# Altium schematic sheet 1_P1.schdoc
size 429 x 358 mm; Symbol: Sheet-Symbol_A4; Device: Sheet-Symbol_A4; Company: 嘉立创EDA; Drawed: Solituder; Version: V4.0; Page Size: A4; @Project Name: FOC12; @Page Count: 1; @Update Date: 2025-03-15; @Create Date: 2024-12-24; @Schematic Name: Schematic2; @Page No: 1; @Page Name: P1; @Board Name: 控制板; @Create Time: 09:32:19; @Update Time: 14:25:51; Width: 1655; Height: 1370; Region Start: 2; X Region Count: 6; Y Region Count: 4; Blade Width: 10; Title Block Position: 3
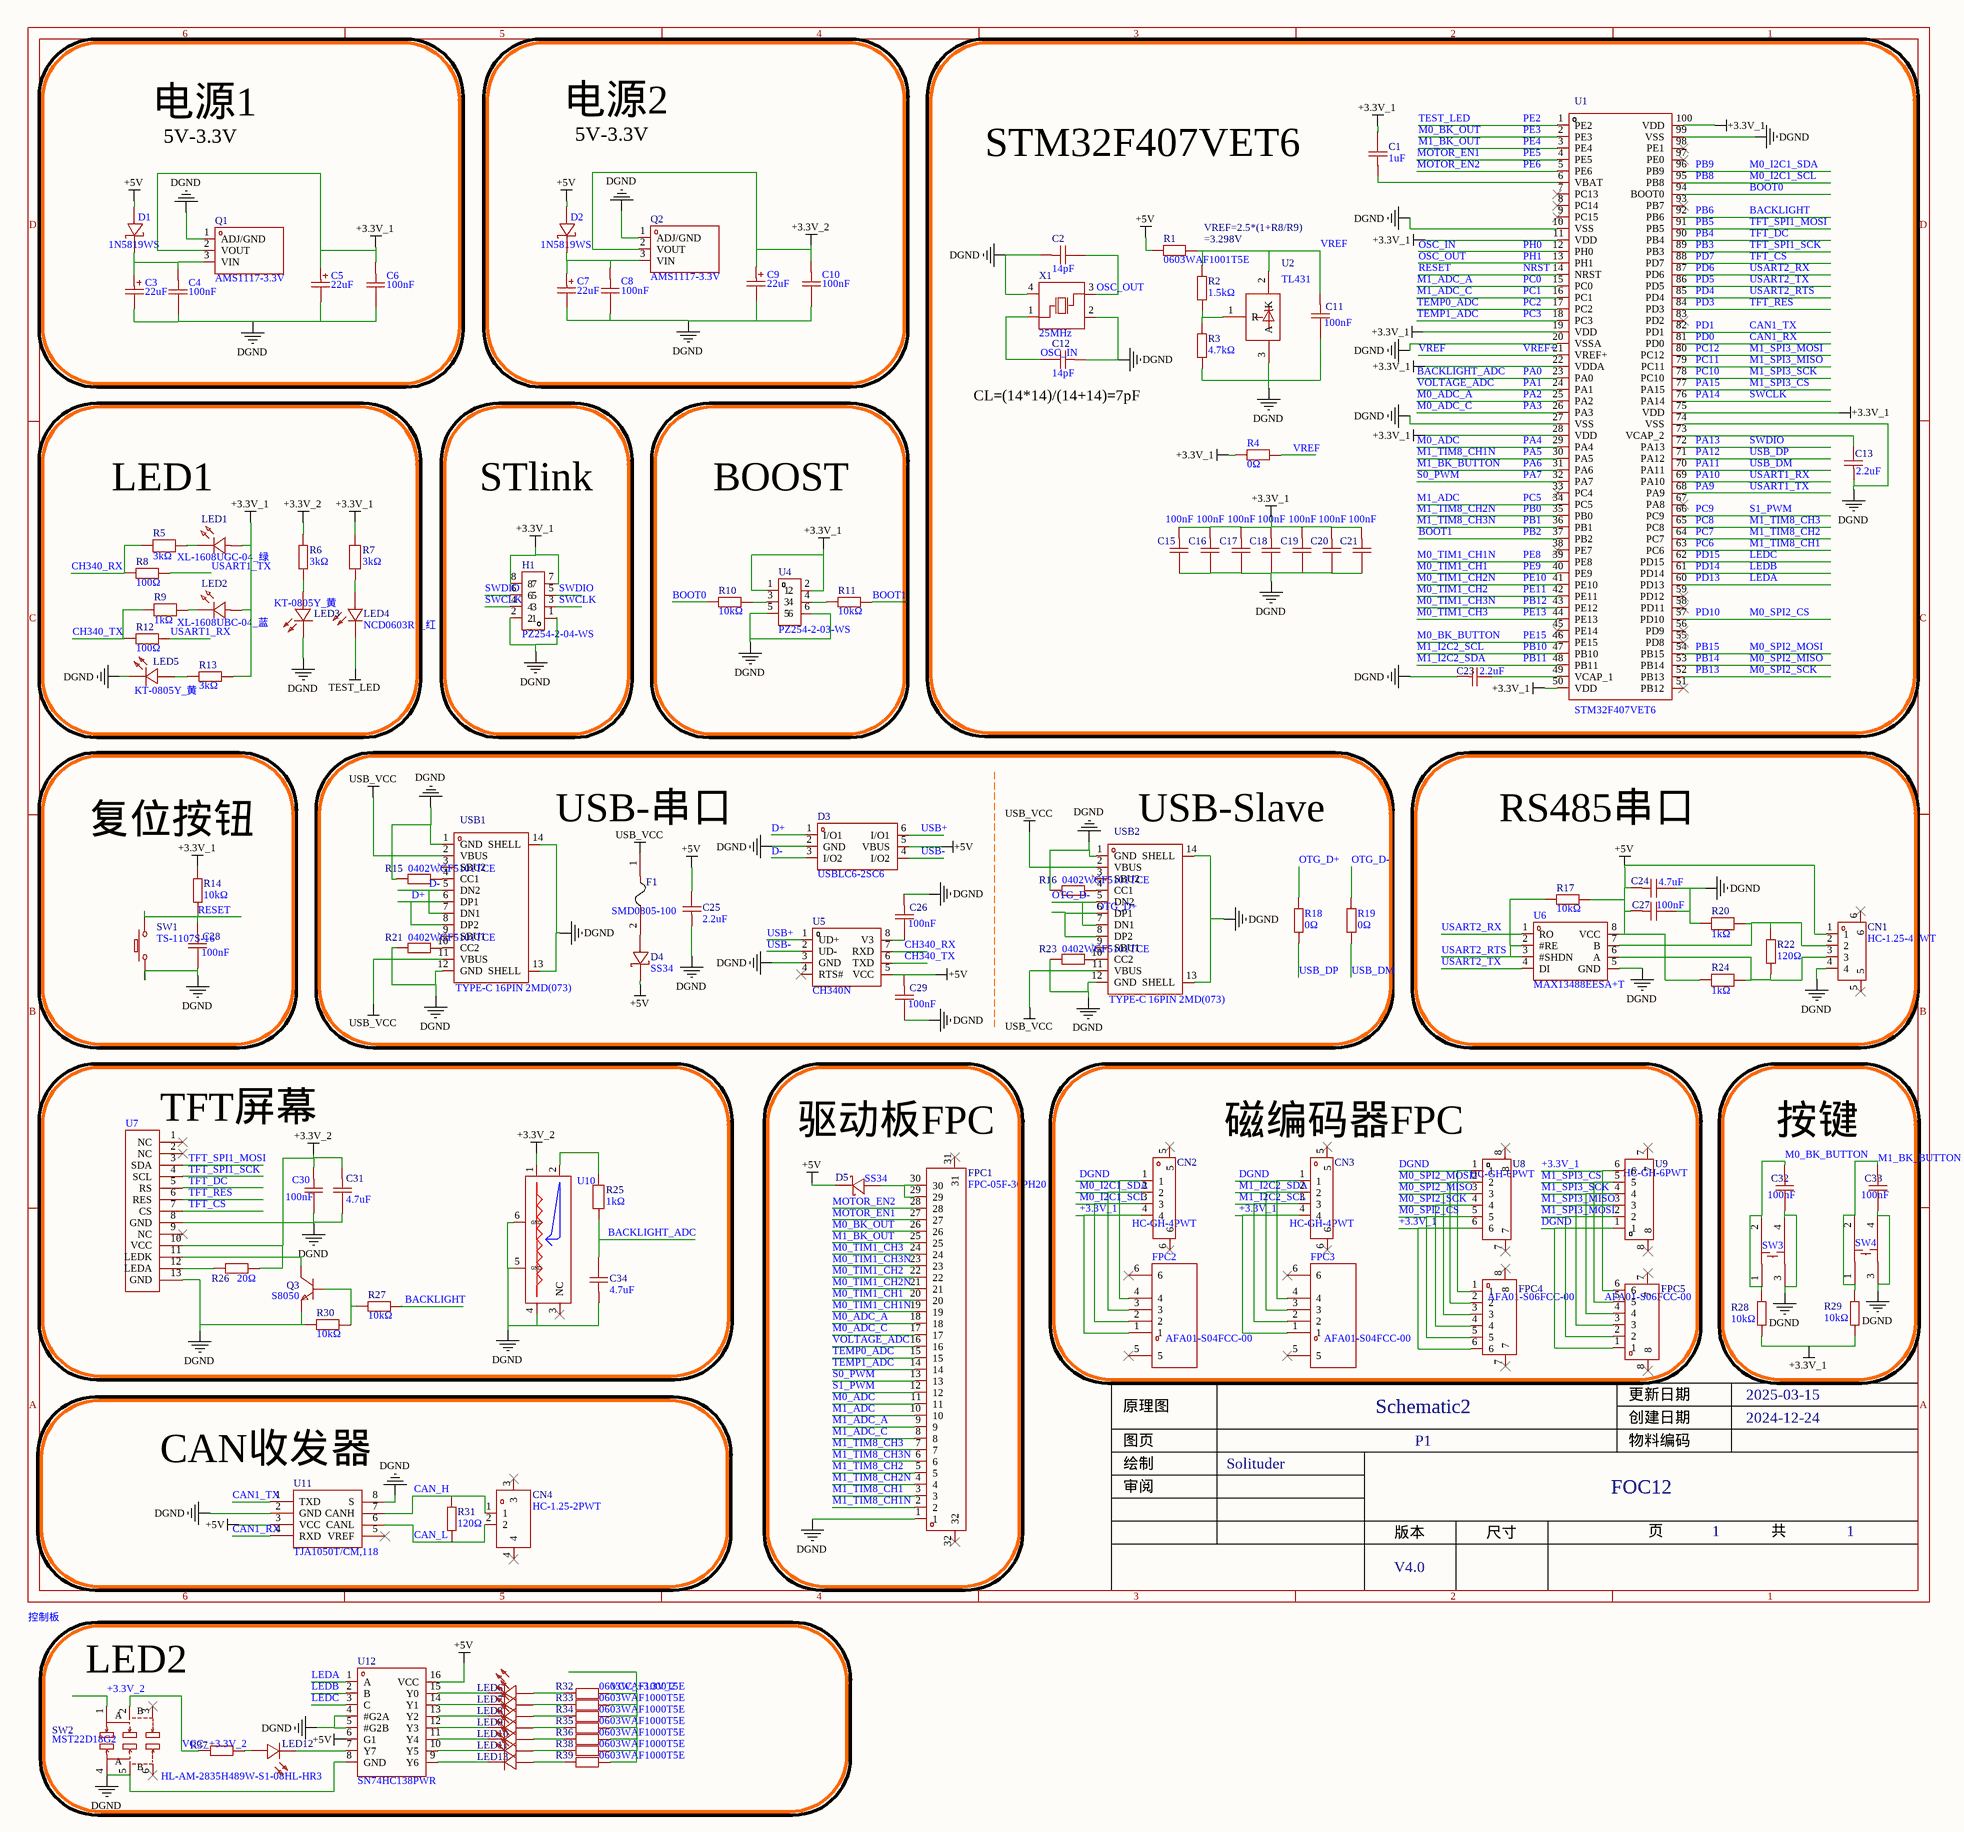
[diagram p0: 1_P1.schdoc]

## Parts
C1  1uF  [C0603]
C2  14pF  [C0402]
C3  22uF  [CASE-A_3216]
C4  100nF  [C0603]
C5  22uF  [CASE-A_3216]
C6  100nF  [C0603]
C7  22uF  [CASE-A_3216]
C8  100nF  [C0603]
C9  22uF  [CASE-A_3216]
C10  100nF  [C0603]
C11  100nF  [C0603]
C12  14pF  [C0402]
C13  2.2uF  [C0603]
C15  100nF  [C0603]
C16  100nF  [C0603]
C17  100nF  [C0603]
C18  100nF  [C0603]
C19  100nF  [C0603]
C20  100nF  [C0603]
C21  100nF  [C0603]
C23  2.2uF  [C0603]
C24  4.7uF  [C0603]
C25  2.2uF  [C0603]
C26  100nF  [C0603]
C27  100nF  [C0603]
C28  100nF  [C0603]
C29  100nF  [C0603]
C30  100nF  [C0603]
C31  4.7uF  [C0603]
C32  100nF  [C0603]
C33  100nF  [C0603]
C34  4.7uF  [C0603]
CN1  HC-1.25-4PWT  [CONN-SMD_4P-P1.25-HC-1.25-4PWT]
CN2  HC-GH-4PWT  [CONN-SMD_HC-GH-4PWT]
CN3  HC-GH-4PWT  [CONN-SMD_HC-GH-4PWT]
CN4  HC-1.25-2PWT  [CONN-SMD_2P-P1.25-HC-1.25-2PWT]
D1  1N5819WS  [SOD-323_L1.8-W1.3-LS2.5-RD]
D2  1N5819WS  [SOD-323_L1.8-W1.3-LS2.5-RD]
D3  USBLC6-2SC6  [SOT-23-6_L2.9-W1.6-P0.95-LS2.8-BL]
D4  SS34  [SMA_L4.3-W2.6-LS5.2-RD]
D5  SS34  [SMA_L4.3-W2.6-LS5.2-RD]
F1  SMD0805-100  [F0805]
FPC1  FPC-05F-30PH20  [FPC-SMD_30P-P0.50_XUNPU_FPC-05F-30PH20]
FPC2  AFA01-S04FCC-00  [FPC-SMD_AFA01-S04FCC-00]
FPC3  AFA01-S04FCC-00  [FPC-SMD_AFA01-S04FCC-00]
FPC4  AFA01-S06FCC-00  [FPC-SMD_6P-P1.00_AFA01-S06]
FPC5  AFA01-S06FCC-00  [FPC-SMD_6P-P1.00_AFA01-S06]
H1  PZ254-2-04-WS  [HDR-SMD_8P-P2.54-H-M-R2-C4_2]
LED1  XL-1608UGC-04_绿  [LED0603-RD_GREEN]
LED2  XL-1608UBC-04_蓝  [LED0603-RD_BLUE]
LED3  KT-0805Y_黄  [LED0805-R-RD]
LED4  NCD0603R1_红  [LED0603-RD_RED]
LED5  KT-0805Y_黄  [LED0805-R-RD]
LED6  HL-AM-2835H489W-S1-08HL-HR3  [LED-SMD_L3.3-W2.8-RD]  (value not drawn)
LED7  HL-AM-2835H489W-S1-08HL-HR3  [LED-SMD_L3.3-W2.8-RD]  (value not drawn)
LED8  HL-AM-2835H489W-S1-08HL-HR3  [LED-SMD_L3.3-W2.8-RD]  (value not drawn)
LED9  HL-AM-2835H489W-S1-08HL-HR3  [LED-SMD_L3.3-W2.8-RD]  (value not drawn)
LED10  HL-AM-2835H489W-S1-08HL-HR3  [LED-SMD_L3.3-W2.8-RD]  (value not drawn)
LED11  HL-AM-2835H489W-S1-08HL-HR3  [LED-SMD_L3.3-W2.8-RD]  (value not drawn)
LED12  HL-AM-2835H489W-S1-08HL-HR3  [LED-SMD_L3.3-W2.8-RD]
LED13  HL-AM-2835H489W-S1-08HL-HR3  [LED-SMD_L3.3-W2.8-RD]  (value not drawn)
Q1  AMS1117-3.3V  [SOT-89-3_L4.5-W2.5-P1.50-LS4.2-BR]
Q2  AMS1117-3.3V  [SOT-89-3_L4.5-W2.5-P1.50-LS4.2-BR]
Q3  S8050  [SOT-23-3_L2.9-W1.3-P1.90-LS2.4-BR]
R1  0603WAF1001T5E  [R0603]
R2  1.5kΩ  [R0603]
R3  4.7kΩ  [R0603]
R4  0Ω  [R0603]
R5  3kΩ  [R0402]
R6  3kΩ  [R0603]
R7  3kΩ  [R0402]
R8  100Ω  [R0402]
R9  1kΩ  [R0402]
R10  10kΩ  [R0402]
R11  10kΩ  [R0402]
R12  100Ω  [R0402]
R13  3kΩ  [R0603]
R14  10kΩ  [R0402]
R15  0402WGF5101TCE  [R0402]
R16  0402WGF5101TCE  [R0402]
R17  10kΩ  [R0402]
R18  0Ω  [R0603]
R19  0Ω  [R0603]
R20  1kΩ  [R0402]
R21  0402WGF5101TCE  [R0402]
R22  120Ω  [R0603]
R23  0402WGF5101TCE  [R0402]
R24  1kΩ  [R0402]
R25  1kΩ  [R0402]
R26  20Ω  [R0402]
R27  10kΩ  [R0402]
R28  10kΩ  [R0402]
R29  10kΩ  [R0402]
R30  10kΩ  [R0402]
R31  120Ω  [R0603]
R32  0603WAF1000T5E  [R0603]
R33  0603WAF1000T5E  [R0603]
R34  0603WAF1000T5E  [R0603]
R35  0603WAF1000T5E  [R0603]
R36  0603WAF1000T5E  [R0603]
R37  0603WAF1000T5E  [R0603]  (value not drawn)
R38  0603WAF1000T5E  [R0603]
R39  0603WAF1000T5E  [R0603]
SW1  TS-1107S-16  [SW-SMD_L6.0-W3.7-LS8.0]
SW2  MST22D18G2  [SW-SMD_MST22D18G2]
SW3  K2-1808SN-A3SW-01  [椭圆白头按钮开关]  (value not drawn)
SW4  K2-1808SN-A3SW-01  [椭圆白头按钮开关]  (value not drawn)
U1  STM32F407VET6  [LQFP-100_L14.0-W14.0-P0.50-LS16.0-BL]
U2  TL431  [SOT-23-3_L2.9-W1.4-P1.90-LS2.6-BR]
U4  PZ254-2-03-WS  [HDR-SMD_6P-P2.54-H-M-R2-C3-LS17.0]
U5  CH340N  [SOP-8_L4.9-W3.9-P1.27-LS6.0-BL]
U6  MAX13488EESA+T  [SOIC-8_L5.0-W4.0-P1.27-LS6.0-BL]
U7  (no value)  [1.14 TFT_13P]
U8  HC-GH-6PWT  [CONN-SMD_6P-P1.25_HCTL_HC-GH-6PWT]
U9  HC-GH-6PWT  [CONN-SMD_6P-P1.25_HCTL_HC-GH-6PWT]
U10  (no value)  [RS08U111Z001]
U11  TJA1050T/CM,118  [SOIC-8_L5.0-W4.0-P1.27-LS6.0-BL]
U12  SN74HC138PWR  [TSSOP-16_L5.0-W4.4-P0.65-LS6.4-BL]
USB1  TYPE-C 16PIN 2MD(073)  [USB-C-SMD_TYPE-C-6PIN-2MD-073]
USB2  TYPE-C 16PIN 2MD(073)  [USB-C-SMD_TYPE-C-6PIN-2MD-073]
X1  25MHz  [CRYSTAL-SMD_4P-L3.2-W2.5-BL]

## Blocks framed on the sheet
电源1: C3-C6 D1 Q1
电源2: C7-C10 D2 Q2
STM32F407VET6: C1 C2 C11-C13 C15-C21 C23 R1-R4 U1 U2 X1
LED1: LED1-LED5 R5-R9 R12 R13
STlink: H1
BOOST: R10 R11 U4
复位按钮: C28 R14 SW1
RS485串口: C24 C27 CN1 R17 R20 R22 R24 U6
TFT屏幕: C30 C31 C34 Q3 R25-R27 R30 U7 U10
驱动板FPC: D5 FPC1
磁编码器FPC: CN2 CN3 FPC2-FPC5 U8 U9
按键: C32 C33 R28 R29 SW3 SW4
CAN收发器: CN4 R31 U11
LED2: LED6-LED13 R32-R39 SW2 U12

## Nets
+3.3V_1: C1.1 C5.1 C6.2 C15.2 C16.2 C17.2 C18.2 C19.2 C20.2 C21.2 CN2.4 CN3.4 FPC2.1 FPC3.1 FPC4.6 FPC5.6 H1.7 H1.8 LED1.2(A) LED2.2(A) Q1.2(VOUT) R4.1 R7.2 R13.2 R14.2 R28.1 R29.1 U1.11(VDD) U1.19(VDD) U1.22(VDDA) U1.28(VDD) U1.50(VDD) U1.75(VDD) U1.100(VDD) U4.1 U4.2 U8.6 U9.6
+3.3V_2: C9.1 C10.2 C30.2 C31.2 Q2.2(VOUT) R6.2 R26.2 SW2.1 U7.10(VCC) U10.1(V/G)
+5V: C24.2 C25.2 C27.2 C29.2 CN1.1 D1.2(A) D2.2(A) D3.5(VBUS) D4.1(K) D5.1(K) R1.1 R17.1 R24.2 U5.5(VCC) U6.8(VCC) U11.3(VCC) U12.6(G1) U12.16(VCC)
DGND: C2.2 C3.2 C4.1 C5.2 C6.1 C7.2 C8.1 C9.2 C10.1 C11.1 C12.2 C13.1 C15.1 C16.1 C17.1 C18.1 C19.1 C20.1 C21.1 C23.1 C24.1 C25.1 C26.2 C27.1 C28.1 C29.1 C30.1 C31.1 C32.1 C33.1 C34.2 CN1.4 CN2.1 CN3.1 D3.2(GND) FPC1.1 FPC2.4 FPC3.4 FPC4.1 FPC5.1 H1.1 H1.2 LED3.2(-) LED5.2(-) Q1.1(ADJ/GND) Q2.1(ADJ/GND) Q3.2(E) R3.1 R15.1 R16.1 R20.2 R21.1 R23.1 R30.2 SW1.1 SW2.4 SW2.5 SW3.3 SW3.4 SW4.3 SW4.4 U1.10(VSS) U1.20(VSSA) U1.27(VSS) U1.74(VSS) U1.99(VSS) U2.3(A) U4.5 U4.6 U5.3(GND) U6.5(GND) U7.8(GND) U7.13(GND) U8.1 U9.1 U10.4(V/G) U10.5(GND) U10.6(GND) U11.2(GND) U11.8(S) U12.4(#G2A) U12.5(#G2B) U12.8(GND) USB1.1(GND) USB1.12(GND) USB1.13(SHELL) USB1.14(SHELL) USB2.1(GND) USB2.12(GND) USB2.13(SHELL) USB2.14(SHELL) X1.2(GND) X1.4(GND)
PE2: LED4.1(K) U1.1(PE2)  [also labelled TEST_LED]
USB_VCC: F1.1 USB1.2(VBUS) USB1.11(VBUS) USB2.2(VBUS) USB2.11(VBUS)
BACKLIGHT: R27.1 U1.92(PB6)  [also labelled PB6]
BACKLIGHT_ADC: C34.1 R25.1 U1.23(PA0)  [also labelled PA0]
BOOT0: R10.1 U1.94(BOOT0)
BOOT1: R11.1 U1.37(PB2)  [also labelled PB2]
CAN1_RX: U1.81(PD0) U11.4(RXD)  [also labelled PD0]
CAN1_TX: U1.82(PD1) U11.1(TXD)  [also labelled PD1]
CAN_H: CN4.1 R31.2 U11.7(CANH)
CAN_L: CN4.2 R31.1 U11.6(CANL)
CH340_RX: R5.2 R8.1 U5.7(RXD)
CH340_TX: R9.2 R12.1 U5.6(TXD)
D+: D3.1(I/O1) USB1.6(DP1) USB1.8(DP2)
D-: D3.3(I/O2) USB1.5(DN2) USB1.7(DN1)
LEDA: U1.60(PD13) U12.1(A)  [also labelled PD13]
LEDB: U1.61(PD14) U12.2(B)  [also labelled PD14]
LEDC: U1.62(PD15) U12.3(C)  [also labelled PD15]
M0_ADC: FPC1.11 U1.29(PA4)  [also labelled PA4]
M0_ADC_A: FPC1.18 U1.25(PA2)  [also labelled PA2]
M0_ADC_C: FPC1.17 U1.26(PA3)  [also labelled PA3]
M0_BK_BUTTON: C32.2 R28.2 SW3.1 SW3.2 U1.46(PE15)  [also labelled PE15]
M0_BK_OUT: FPC1.26 U1.2(PE3)  [also labelled PE3]
M0_I2C1_SCL: CN2.3 FPC2.2 U1.95(PB8)  [also labelled PB8]
M0_I2C1_SDA: CN2.2 FPC2.3 U1.96(PB9)  [also labelled PB9]
M0_SPI2_CS: FPC4.5 U1.57(PD10) U8.5  [also labelled PD10]
M0_SPI2_MISO: FPC4.3 U1.53(PB14) U8.3  [also labelled PB14]
M0_SPI2_MOSI: FPC4.2 U1.54(PB15) U8.2  [also labelled PB15]
M0_SPI2_SCK: FPC4.4 U1.52(PB13) U8.4  [also labelled PB13]
M0_TIM1_CH1: FPC1.20 U1.40(PE9)  [also labelled PE9]
M0_TIM1_CH1N: FPC1.19 U1.39(PE8)  [also labelled PE8]
M0_TIM1_CH2: FPC1.22 U1.42(PE11)  [also labelled PE11]
M0_TIM1_CH2N: FPC1.21 U1.41(PE10)  [also labelled PE10]
M0_TIM1_CH3: FPC1.24 U1.44(PE13)  [also labelled PE13]
M0_TIM1_CH3N: FPC1.23 U1.43(PE12)  [also labelled PB12]
M1_ADC: FPC1.10 U1.34(PC5)  [also labelled PC5]
M1_ADC_A: FPC1.9 U1.15(PC0)  [also labelled PC0]
M1_ADC_C: FPC1.8 U1.16(PC1)  [also labelled PC1]
M1_BK_BUTTON: C33.2 R29.2 SW4.1 SW4.2 U1.31(PA6)  [also labelled PA6]
M1_BK_OUT: FPC1.25 U1.3(PE4)  [also labelled PE4]
M1_I2C2_SCL: CN3.3 FPC3.2 U1.47(PB10)  [also labelled PB10]
M1_I2C2_SDA: CN3.2 FPC3.3 U1.48(PB11)  [also labelled PB11]
M1_SPI3_CS: FPC5.5 U1.77(PA15) U9.5  [also labelled PA15]
M1_SPI3_MISO: FPC5.3 U1.79(PC11) U9.3  [also labelled PC11]
M1_SPI3_MOSI: FPC5.2 U1.80(PC12) U9.2  [also labelled PC12]
M1_SPI3_SCK: FPC5.4 U1.78(PC10) U9.4  [also labelled PC10]
M1_TIM8_CH1: FPC1.3 U1.63(PC6)  [also labelled PC6]
M1_TIM8_CH1N: FPC1.2 U1.30(PA5)  [also labelled PA5]
M1_TIM8_CH2: FPC1.5 U1.64(PC7)  [also labelled PC7]
M1_TIM8_CH2N: FPC1.4 U1.35(PB0)  [also labelled PB0]
M1_TIM8_CH3: FPC1.7 U1.65(PC8)  [also labelled PC8]
M1_TIM8_CH3N: FPC1.6 U1.36(PB1)  [also labelled PB1]
MOTOR_EN1: FPC1.27 U1.4(PE5)  [also labelled PE5]
MOTOR_EN2: FPC1.28 U1.5(PE6)  [also labelled PE6]
NRST: C28.2 R14.1 SW1.2 U1.14(NRST)  [also labelled RESET]
OSC_IN: C12.1 U1.12(PH0) X1.1(OSC1)  [also labelled PH0]
OSC_OUT: C2.1 U1.13(PH1) X1.3(OSC2)  [also labelled PH1]
OTG_D+: R18.1 USB2.6(DP1) USB2.8(DP2)
OTG_D-: R19.1 USB2.5(DN2) USB2.7(DN1)
PA1: FPC1.16 U1.24(PA1)  [also labelled VOLTAGE_ADC]
PA7: FPC1.13 U1.32(PA7)  [also labelled S0_PWM]
PA9: R8.2 U1.68(PA9)  [also labelled USART1_TX]
PA10: R12.2 U1.69(PA10)  [also labelled USART1_RX]
PA11: R19.2 U1.70(PA11)  [also labelled USB_DM]
PA12: R18.2 U1.71(PA12)  [also labelled USB_DP]
PA13: H1.5 H1.6 U1.72(PA13)  [also labelled SWDIO]
PA14: H1.3 H1.4 U1.76(PA14)  [also labelled SWCLK]
PB3: U1.89(PB3) U7.4(SCL)  [also labelled TFT_SPI1_SCK]
PB4: U1.90(PB4) U7.5(RS)  [also labelled TFT_DC]
PB5: U1.91(PB5) U7.3(SDA)  [also labelled TFT_SPI1_MOSI]
PC2: FPC1.15 U1.17(PC2)  [also labelled TEMP0_ADC]
PC3: FPC1.14 U1.18(PC3)  [also labelled TEMP1_ADC]
PC9: FPC1.12 U1.66(PC9)  [also labelled S1_PWM]
PD3: U1.84(PD3) U7.6(RES)  [also labelled TFT_RES]
PD4: R17.2 U1.85(PD4) U6.2(#RE) U6.3(#SHDN)  [also labelled USART2_RTS]
PD5: U1.86(PD5) U6.4(DI)  [also labelled USART2_TX]
PD6: U1.87(PD6) U6.1(RO)  [also labelled USART2_RX]
PD7: U1.88(PD7) U7.7(CS)  [also labelled TFT_CS]
USB+: D3.6(I/O1) U5.1(UD+)
USB-: D3.4(I/O2) U5.2(UD-)
VCC_+3.3V_2: R32.2 R33.2 R34.2 R35.2 R36.2 R37.2 R38.2 R39.2 SW2.2
VREF: C11.2 R1.2 R2.2 R4.2 U1.21(VREF+) U2.2(K)  [also labelled VREF+]
NetC1_2: C1.2 U1.6(VBAT)
NetC3_1: C3.1 C4.2 D1.1(K) Q1.3(VIN)
NetC7_1: C7.1 C8.2 D2.1(K) Q2.3(VIN)
NetC13_2: C13.2 U1.73(VCAP_2)
NetC23_2: C23.2 U1.49(VCAP_1)
NetC26_1: C26.1 U5.8(V3)
NetCN1_2: CN1.2 R20.1 R22.2 U6.7(B)
NetCN1_3: CN1.3 R22.1 R24.1 U6.6(A)
NetD4_2: D4.2(A) F1.2
NetD5_2: D5.2(A) FPC1.29 FPC1.30
NetLED1_1: LED1.1(K) R5.1
NetLED2_1: LED2.1(K) R9.1
NetLED3_1: LED3.1(+) R6.1
NetLED4_2: LED4.2(A) R7.1
NetLED5_1: LED5.1(+) R13.1
NetLED6_1: LED6.1 U12.15(Y0)
NetLED6_2: LED6.2 R32.1
NetLED7_1: LED7.1 U12.14(Y1)
NetLED7_2: LED7.2 R33.1
NetLED8_1: LED8.1 U12.13(Y2)
NetLED8_2: LED8.2 R34.1
NetLED9_1: LED9.1 U12.12(Y3)
NetLED9_2: LED9.2 R35.1
NetLED10_1: LED10.1 U12.11(Y4)
NetLED10_2: LED10.2 R36.1
NetLED11_1: LED11.1 U12.10(Y5)
NetLED11_2: LED11.2 R38.1
NetLED12_1: LED12.1 U12.7(Y7)
NetLED12_2: LED12.2 R37.1
NetLED13_1: LED13.1 U12.9(Y6)
NetLED13_2: LED13.2 R39.1
NetQ3_1: Q3.1(B) R27.2 R30.1
NetQ3_3: Q3.3(C) U7.11(LEDK)
NetR2_1: R2.1 R3.2 U2.1(R)
NetR10_2: R10.2 U4.3
NetR11_2: R11.2 U4.4
NetR15_2: R15.2 USB1.4(CC1)
NetR16_2: R16.2 USB2.4(CC1)
NetR21_2: R21.2 USB1.10(CC2)
NetR23_2: R23.2 USB2.10(CC2)
NetR25_2: R25.2 U10.2(OUT)
NetR26_1: R26.1 U7.12(LEDA)

Not connected (* = marked no-connect by the designer): CN1 5* 6*; CN2 5* 6*; CN3 5* 6*; CN4 3* 4*; FPC1 31* 32*; FPC2 5* 6*; FPC3 5* 6*; FPC4 7* 8*; FPC5 7* 8*; SW2 3* 6*; U1 7(PC13)* 8(PC14)* 9(PC15)* 33(PC4)* 38(PE7)* 45(PE14)* 51(PB12)* 55(PD8)* 56(PD9)* 58(PD11)* 59(PD12)* 67(PA8)* 83(PD2)* 93(PB7)* 97(PE0)* 98(PE1)*; U5 4(RTS#)*; U7 1(NC)* 2(NC)* 9(NC)*; U8 7* 8*; U9 7* 8*; U10 3(NC)*; U11 5(VREF)*; USB1 3(SBU2)* 9(SBU1)*; USB2 3(SBU2)* 9(SBU1)*

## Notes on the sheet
- 5V-3.3V
- VREF=2.5*(1+R8/R9)
  =3.298V
- (near C12) CL=(14*14)/(14+14)=7pF
- USB-串口
- (near USB2) USB-Slave

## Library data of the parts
C1 = CL10A105KB8NNNC: Manufacturer: SAMSUNG(三星); Add into BOM: yes; Tolerance: ±10%; Voltage Rated: 50V; Temperature Coefficient: X5R
C2 C12 = 0402CG140J500NT: Manufacturer: FH(风华); Add into BOM: yes; Tolerance: ±5%; Voltage Rated: 50V; Temperature Coefficient: C0G
C3 C5 C7 C9 = TAJA226K010RNJ: Manufacturer: Kyocera AVX; Add into BOM: yes; Tolerance: ±10%; Rated Voltage: 10V; Equivalent Series Resistance(ESR): 3Ω@100kHz
C4 C6 C8 C10 C30 = CC0603KRX7R9BB104: Manufacturer: YAGEO(国巨); Add into BOM: yes; Tolerance: ±10%; Voltage Rated: 50V; Temperature Coefficient: X7R
C11 C15-C21 C26-C29 C32 C33 = CGA0603X7R104K500JT: Manufacturer: HRE(芯声); Add into BOM: yes; Tolerance: ±10%; Voltage Rated: 50V; Temperature Coefficient: X7R
C13 C23 C25 = CL10A225KO8NNNC: Manufacturer: SAMSUNG(三星); Add into BOM: yes; Tolerance: ±10%; Voltage Rated: 16V; Temperature Coefficient: X5R
C24 C31 C34 = CL10A475KO8NNNC: Manufacturer: SAMSUNG(三星); Add into BOM: yes; Tolerance: ±10%; Voltage Rated: 16V; Temperature Coefficient: X5R
CN1 = HC-1.25-4PWT: Manufacturer: HCTL(华灿天禄); Add into BOM: yes; Pins Structure: 1x4P; Pitch: 1.25mm; Reference Series: PicoBlade(MX 1.25); Number of PINs Per Row: 4; Current Rating (Max): 1A; Rated Voltage (Max): 125V; Plastic Material: LCP; Flame Retardant Rating: UL94V-0; Supplementary Features: 辅助焊脚; Z-Height of the Board: 3.57mm; X-Length of Bottom Edge on Board (Spacing Line): 10.05mm; Y-Width of Bottom Edge on Board: 5.25mm
CN2 CN3 = HC-GH-4PWT_C2845399: Manufacturer: HCTL(华灿天禄); Add into BOM: yes; Pins Structure: 1x4P; Pitch: 1.25mm; Reference Series: GH; Number of PINs Per Row: 4; Current Rating (Max): 1A; Rated Voltage (Max): 50V; Plastic Material: LCP; Flame Retardant Rating: UL94V-0; Supplementary Features: 辅助焊脚; Z-Height of the Board: 4.25mm; X-Length of Bottom Edge on Board (Spacing Line): 8.25mm
CN4 = HC-1.25-2PWT: Manufacturer: HCTL(华灿天禄); Add into BOM: yes; Pins Structure: 1x2P; Pitch: 1.25mm; Reference Series: PicoBlade(MX 1.25); Number of PINs Per Row: 2; Current Rating (Max): 1A; Rated Voltage (Max): 125V; Plastic Material: LCP; Flame Retardant Rating: UL94V-0; Supplementary Features: 辅助焊脚; Z-Height of the Board: 3.57mm; X-Length of Bottom Edge on Board (Spacing Line): 7.55mm; Y-Width of Bottom Edge on Board: 5.25mm
D1 D2 = 1N5819WS_C191023: Manufacturer: Hottech(合科泰); Add into BOM: yes; Reverse Voltage (Vr): 40V; Average Rectified Current (Io): 1A; Forward Voltage (Vf@If): 600mV@1A
D3 = USBLC6-2SC6: Manufacturer: UMW(友台半导体); Symbol: USBLC6-2SC6_C2687116; Add into BOM: yes; Maximum Clamping Voltage: 15V; Breakdown Voltage: 6V; Number of Lines: 双路; Type: ESD
D4 D5 = SS34_C8678: Manufacturer: MDD(辰达半导体); Add into BOM: yes; Diode Configuration: 独立式; Forward Voltage (Vf@If): 550mV@3A; Reverse Voltage (Vr): 40V; Rectified Current: 3A; Reverse Leakage Current (Ir): 500uA@40V
F1 = SMD0805-100: Manufacturer: 台湾陆海; Add into BOM: yes; Operating Voltage (Max): 6V; Current Rating (Max): 100A; Hold Current: 1A; Trip Current: 1.95A
FPC1 = FPC-05F-30PH20: Manufacturer: XUNPU(讯普); Add into BOM: yes; Locking Feature: 翻盖式; Number of Contacts: 30P; Pitch: 0.5mm; FFC, FCB Thickness: 0.3mm
FPC2 FPC3 = AFA01-S04FCC-00: Manufacturer: JS(钜硕电子); Add into BOM: yes; Pitch: 1mm; Number of Contacts: 4; Locking Feature: 翻盖式; FFC, FCB Thickness: 0.3mm
FPC4 FPC5 = AFA01-S06FCC-00: Manufacturer: JS(钜硕电子); Add into BOM: yes; Locking Feature: 翻盖式; Number of Contacts: 6; Pitch: 1mm; FFC, FCB Thickness: 0.3mm
H1 = PZ254-2-04-WS: Manufacturer: HCTL(华灿天禄); Add into BOM: yes; Pin Structure: 2x4P; Pitch: 2.54mm; Circluar Pins/Square Pins: 方针; Current Rating (Max): 3A; Soldering Temperature(Max): 260℃@10S
LED1 = XL-1608UGC-04: Manufacturer: XINGLIGHT(成兴光); Add into BOM: yes; Emitted Color: 翠绿色; Power Dissipation: 80mW; Forward Current: 25mA; Dominant Wavelength: 516nm~525nm; Peak Wavelength: 534nm; Diode Configuration: 独立二极管; Lens Color: 无色透明透镜; Viewing Angle: 120°; Mounting Sytle: 正贴
LED2 = XL-1608UBC-04: Manufacturer: XINGLIGHT(成兴光); Add into BOM: yes; Emitted Color: 蓝色; Power Dissipation: 80mW; Forward Current: 25mA; Dominant Wavelength: 460nm~469nm; Peak Wavelength: 475nm; Lens Color: 无色透明透镜; Viewing Angle: 120°; Mounting Sytle: 正贴
LED3 LED5 = KT-0805Y: Manufacturer: KENTO; Symbol: 17-21SUYC/TR8; Add into BOM: yes; Emitted Color: 黄色
LED4 = NCD0603R1_C84263: Manufacturer: 国星光电; Symbol: FC-DA1608HRK-620D; Add into BOM: yes; Forward Current: 25mA; Diode Configuration: 独立二极管; Luminous Intensity: 80mcd~220mcd; Viewing Angle: 130°; Illumination Color: 红色; Voltage - Forward(Vf): 1.6V~2.6V; Power(Watts): 65mW; Wavelength - Dominant: 615nm~630nm
LED6-LED13 = HL-AM-2835H489W-S1-08HL-HR3: Manufacturer: HONGLITRONIC(鸿利光电); Symbol: HL-AM-2835H489W-S1-08HL-HR3_C210310; Add into BOM: yes; Emitted Color: 白灯; Color Temperature: 2800K~3100K; Mounting Sytle: 正贴
Q1 Q2 = AMS1117-3.3V_C5120796: Manufacturer: MSKSEMI(美森科); Add into BOM: yes; Output Type: 固定; Maximum Input Voltage: 18V; Output Voltage: 3.3V; MAX Output Current: 1A; Dropout Voltage: 1.4V@(1A); standby current: 12mA; Output Polarity: 正极; Number of Outputs: 1
Q3 = S8050: Manufacturer: Doeshare(德芯); Symbol: S8050_C2931719; Add into BOM: yes
R1 = 0603WAF1001T5E: Manufacturer: UNI-ROYAL(厚声); Add into BOM: yes
R2 = 0603WAF1501T5E: Manufacturer: UNI-ROYAL(厚声); Add into BOM: yes; Tolerance: ±1%; Power(Watts): 1/10W; Overload Voltage (Max): 75V; Temperature Coefficient: ±100ppm/℃
R3 = RC0603FR-074K7L: Manufacturer: YAGEO(国巨); Add into BOM: yes; Tolerance: ±1%; Power(Watts): 100mW; Overload Voltage (Max): 75V; Temperature Coefficient: ±100ppm/℃
R4 R18 R19 = 0603WAF0000T5E: Manufacturer: UNI-ROYAL(厚声); Add into BOM: yes; Tolerance: ±1%; Power(Watts): 1/10W; Overload Voltage (Max): 75V
R5 R7 = FRC0402F3001TS: Manufacturer: FOJAN(富捷); Add into BOM: yes; Tolerance: ±1%; Power(Watts): 62.5mW; Overload Voltage (Max): 50V; Temperature Coefficient: ±100ppm/℃
R6 R13 = 0603WAF3001T5E: Manufacturer: UNI-ROYAL(厚声); Add into BOM: yes; Tolerance: ±1%; Power(Watts): 100mW; Overload Voltage (Max): 75V; Temperature Coefficient: ±100ppm/℃
R8 R12 = 0402WGF1000TCE: Manufacturer: UNI-ROYAL(厚声); Add into BOM: yes; Tolerance: ±1%; Power(Watts): 1/16W; Overload Voltage (Max): 50V; Temperature Coefficient: ±200ppm/℃
R9 R20 R24 R25 = FRC0402J102 TS: Manufacturer: FOJAN(富捷); Add into BOM: yes; Tolerance: ±5%; Power(Watts): 62.5mW; Overload Voltage (Max): 50V; Temperature Coefficient: ±100ppm/℃
R10 R11 R14 R17 R27-R30 = 0402WGF1002TCE: Manufacturer: UNI-ROYAL(厚声); Add into BOM: yes; Tolerance: ±1%; Power(Watts): 62.5mW; Overload Voltage (Max): 50V; Temperature Coefficient: ±100ppm/℃
R15 R16 R21 R23 = 0402WGF5101TCE: Manufacturer: UNI-ROYAL(厚声); Add into BOM: yes
R22 R31 = 0603WAF1200T5E: Manufacturer: UNI-ROYAL(厚声); Add into BOM: yes; Tolerance: ±1%; Power(Watts): 100mW; Overload Voltage (Max): 75V; Temperature Coefficient: ±100ppm/℃
R26 = 0402WGF200JTCE: Manufacturer: UNI-ROYAL(厚声); Add into BOM: yes; Tolerance: ±1%; Power(Watts): 62.5mW; Overload Voltage (Max): 50V; Temperature Coefficient: ±200ppm/℃
R32-R39 = 0603WAF1000T5E: Manufacturer: UNI-ROYAL(厚声); Add into BOM: yes
SW1 = TS-1107S-16: Manufacturer: SOFNG(硕方); Add into BOM: yes; Circuit: 单刀单掷; Actuator Style: 矩形按钮; Operating Force: 1.6N; Switch Length: 6mm; Switch Width: 3mm; Switch Height: 2.6mm; Contact Current: 25mA; Voltage Rating (DC): 24V; Actuator/Cap Color: 红色; Mechanical Life: 6.5万次
SW2 = MST22D18G2: Manufacturer: SHOU HAN(首韩); Add into BOM: yes; Circuit: 双刀双掷; Pin Style: SMD接片; Switch Length: 9.1mm; Switch Width: 3.6mm; Switch Height: 3.45mm; Current Rating (DC): 50mA; Voltage Rating (DC): 12V; Mechanical Life: 1万次
SW3 SW4 = K2-1808SN-A3SW-01: Manufacturer: 韩国韩荣; Add into BOM: yes; Contact Current: 50mA; Voltage Rating (DC): 12V; Insulation Resistance: 100MΩ; Operating Force: 180gf@±30gf; Mechanical Life: 100000; Switch Length: 4.2mm; Switch Width: 3.25mm; Switch Height: 2.5mm
U1 = STM32F407VGT6: Manufacturer: ST(意法半导体); Add into BOM: yes; CPU Core: ARM-M4; Program Storage Size: 1MB; RAM Size: 192KB; GPIO Ports Number: 82; Operating Voltage Range: 1.8V~3.6V; CPU Maximum Speed: 168MHz; Program Memory Type: FLASH; ADC (Bit): 12bit; Universal Serial Bus: 有; Peripheral/Function: DMA；LCD/LED驱动
U2 = TL431_C963380: Manufacturer: JSMSEMI(杰盛微); Add into BOM: yes; Output Type: 可调; Input Voltage: 37V; Output Voltage: 2.5V~36V; Temperature Coefficient: 50ppm/℃; Reference Type: 并联; Minimum Cathode Current for Regulation: 1mA; Dynamic Impedance: 150mΩ
U4 = PZ254-2-03-WS: Manufacturer: HCTL(华灿天禄); Add into BOM: yes; Pin Structure: 2x3P; Pitch: 2.54mm; Circluar Pins/Square Pins: 方针; Current Rating (Max): 3A; Soldering Temperature(Max): 260℃@10S
U5 = CH340N: Manufacturer: WCH(南京沁恒); Symbol: CH340N_C2977777; Add into BOM: yes; Applications Function: USB转串口; Protocol: USB 2.0; Number of Channels: 1; Supply Voltage: 3.3V；5V; Data Rate: 2Mbps
U6 = MAX13488EESA+T: Manufacturer: ADI(亚德诺)/MAXIM(美信); Add into BOM: yes; Types: 收发器; Driver/receiver: 1/1; Data Rate: 16Mbps; Supply Voltage: 4.75V~5.25V
U7 = 1.14 TFT_13P: Add into BOM: yes
U8 U9 = HC-GH-6PWT: Manufacturer: HCTL(华灿天禄); Symbol: HC-GH-6PWTKK; Add into BOM: yes; Pins Structure: 1x6P; Pitch: 1.25mm; Reference Series: GH; Number of PINs Per Row: 6; Current Rating (Max): 1A; Rated Voltage (Max): 50V; Plastic Material: LCP; Flame Retardant Rating: UL94V-0; Supplementary Features: 辅助焊脚; Z-Height of the Board: 4.25mm; X-Length of Bottom Edge on Board (Spacing Line): 10.75mm
U10 = RS08U111Z001: Part Code: C202411; Manufacturer: ALPSALPINE(阿尔卑斯阿尔派); Resistance: 10K; Add into BOM: yes
U11 = TJA1050T/CM,118: Manufacturer: NXP(恩智浦); Add into BOM: yes; Supply Voltage: 4.75V ~ 5.25V; Protocol: CAN总线
U12 = SN74HC138PWR: Manufacturer: TI(德州仪器); Add into BOM: yes
USB1 USB2 = TYPE-C 16PIN 2MD(073): Manufacturer: SHOU HAN(首韩); Add into BOM: yes; Gender: 母; Number of Ports: 1; Number of Contacts: 16P; Current Rating - Power (Max): 5A
X1 = X322525MOB4SI: Manufacturer: YXC(扬兴晶振); Add into BOM: yes; Crystal Type: 贴片晶振; Normal temperature Frequency Tolerance: ±10ppm; Load Capacitor: 12pF; Frequency Stability(Full temperature range): ±20ppm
